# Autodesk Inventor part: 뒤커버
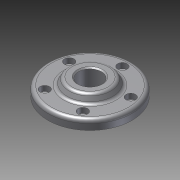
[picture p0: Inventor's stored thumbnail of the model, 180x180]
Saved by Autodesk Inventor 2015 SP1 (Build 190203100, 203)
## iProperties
Company: 한국ATC센터
Created: 2014-03
Part Number: 뒤커버
Document SubType Name: Modeling
Designer: KYOUNG IL JANG
Density: 1 g/cm^3
Material: 일반
Appearance: 기본값
Author: KYOUNG IL JANG
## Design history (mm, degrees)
sketch "스케치1"
  geometry: C1 r 20 at (0, 0); C2 r 35 at (0, 0); 1 further point
  constraints: 2 centre point, 2 coincident
  dimensions: "d0" = 40 diameter of C1; "d1" = 70 diameter of C2
extrude "돌출1" new body sketch "스케치1" distance "d2" = 5; taper "d3" = 0 deg
extrude "돌출2" join sketch "스케치1" distance "d4" = 8; taper "d5" = 0 deg
sketch "스케치2"
  geometry: C1 r 20 at (0, 0); 1 further point
  constraints: 1 centre point, 1 coincident
  dimensions: "d6" = 40 diameter of C1
extrude "돌출3" join sketch "스케치2" distance "d7" = 6; taper "d8" = -30 deg
sketch "스케치3"
  geometry: 2 further points
  constraints: 1 vertical alignment
  dimensions: "d9" = 27 distance of point (0, 0) point (0, 27)
hole "구멍1" sketch "스케치3" at (0, 27) diameter "d10" = 4.5; stored, may be unused: countersink angle "d14" = 90 deg, drill point angle "d16" = 118 deg; dims "d11" = 6, "d12" = 8, "d13" = 4.4, "d15" = 8
hole "구멍2" diameter "d22" = 19; stored, may be unused: countersink angle "d26" = 90 deg, drill point angle "d28" = 118 deg; dims "d20" = 10, "d21" = 10, "d23" = 6, "d24" = 30, "d25" = 3, "d27" = 8
fillet "모깎기1" dims "d29" = 3
chamfer "모따기1" distance "d30" = 1; stored, may be unused: second distance "d31" = 2, angle "d32" = 45 deg
node "솔리드1"
pattern_circular "원형 패턴1" dims angle "d18" = 360 deg
